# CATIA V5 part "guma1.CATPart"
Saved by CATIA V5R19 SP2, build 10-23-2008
Part number: guma
Bounding box of the stored display mesh (mm): x -39.842 to 39.842, y -34 to 34, z -39.842 to 39.842
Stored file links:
  C:\Users\Martiin\Desktop\9.semestr\Projekt-diplomka\3D model\silentbloky\guma1.CATPart
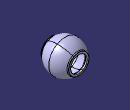
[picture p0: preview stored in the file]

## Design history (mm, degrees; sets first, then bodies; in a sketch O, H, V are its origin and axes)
Body1 (main body)
  Sketch1 on yz-plane, origin (0, 0, 0), H (0, 1, 0), V (0, 0, 1)
    axis line L1 (-72.232, 0) -> (45.0362, 0)
    point P1 (-72.232, 0)
    construction line L2 (0, 70.0582) -> (0, -36.1683)
    point P3 (0, 70.0582)
    line L3 (-34, 20) -> (-30.249, 20)
    line L4 (-34, 24.5) -> (-33.0568, 24.5)
    point P5 (-34.641, 20)
    point P6 (-28.7228, 20)
    line L5 (-34, 24.5) -> (-34, 20)
    arc A1 centre (-30.249, 23) radius 3 from (-27.8609, 21.1842) to (-30.249, 20) cw
    point P7 (-27.8609, 21.1842)
    point P8 (-30.249, 20)
    arc A2 centre (-33.0568, 27.5) radius 3 from (-30.7505, 25.5814) to (-33.0568, 24.5) cw
    point P10 (-30.7505, 25.5814)
    point P11 (-33.0568, 24.5)
    point P13 (-34, 24.5)
    point P14 (-34, 20)
    arc A3 centre (0, 0) radius 35 from (0, 35) to (-27.8609, 21.1842) ccw
    point P15 (0, 35)
    arc A4 centre (0, 0) radius 40 from (0, 40) to (-30.7505, 25.5814) ccw
    point P16 (0, 40)
    point P17 (34.641, 20)
    point P18 (28.7228, 20)
    point P19 (27.8609, 21.1842)
    point P20 (30.249, 20)
    point P22 (30.7505, 25.5814)
    point P23 (33.0568, 24.5)
    point P25 (34, 24.5)
    point P26 (34, 20)
    line L6 (34, 20) -> (30.249, 20)
    line L7 (34, 24.5) -> (33.0568, 24.5)
    line L8 (34, 24.5) -> (34, 20)
    arc A5 centre (30.249, 23) radius 3 from (27.8609, 21.1842) to (30.249, 20) ccw
    arc A6 centre (33.0568, 27.5) radius 3 from (30.7505, 25.5814) to (33.0568, 24.5) ccw
    point P27 (0, 40)
    arc A7 centre (0, 0) radius 40 from (0, 40) to (30.7505, 25.5814) cw
    point P29 (0, 35)
    arc A8 centre (0, 0) radius 35 from (0, 35) to (27.8609, 21.1842) cw
    distance L3 L1 = 20
    distance L4 L1 = 24.5
    distance L5 L2 = 34
    radius A1 = 3
    radius A2 = 3
    radius A3 = 35
    radius A4 = 40
    coincidence: P1 H, P3 V, L3 P5, L3 P6, L2 P15, L2 P16, P15 P29, P16 P27
    horizontal: L1 H, L3 H, L4 H
    vertical: L2 V, L5 V
    tangency: A1 L3, A2 L4
    symmetry: P5 P17 L2, P6 P18 L2, P7 P19 L2, P8 P20 L2, P10 P22 L2, P11 P23 L2, P13 P25 L2, P14 P26 L2, L3 L6 L2, L4 L7 L2, L5 L8 L2, A1 A5 L2, A2 A6 L2, P16 P27 L2, A4 A7 L2, P15 P29 L2, A3 A8 L2
  Shaft1: profile Sketch1, axis Sketch1.L1, angle 360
